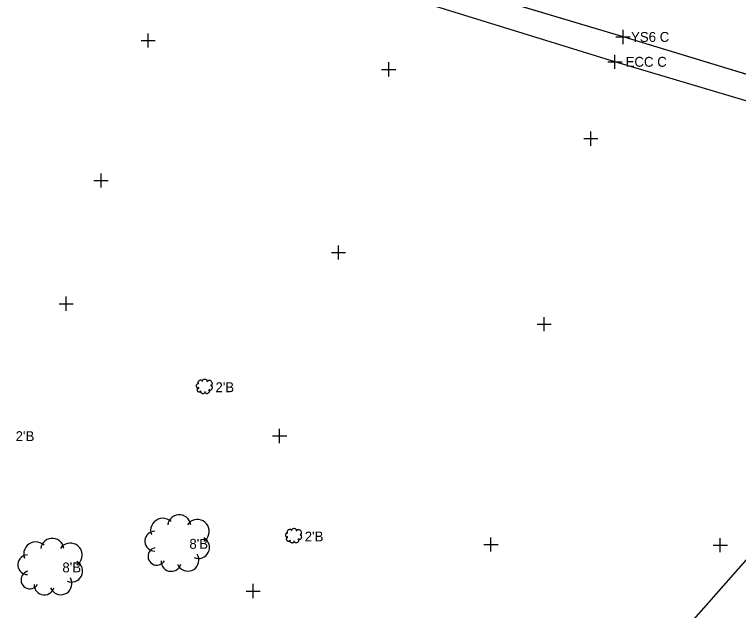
# Model space of a CAD drawing. Extents: x 1324236 to 1326110, y 459090 to 460782.
# Drawn here: x 1325080.9 to 1325183.3, y 460303.9 to 460388.2 of the extents above; entities that cross this region are included whole.
import ezdxf

# ---------------------------------------------------------------- set-up
doc = ezdxf.new("R2010")
doc.units = 0
for name, color, linetype in [('DR_X_Ditch', 7, 'Continuous'), ('DV_X_Property_Line', 7, 'Continuous'), ('E-RW-ODOT', 7, 'Continuous'), ('PM_X_Edge_Line', 7, 'Continuous'), ('PV_X_Shoulder', 7, 'Continuous'), ('RW_X_CL', 7, 'Continuous'), ('VG_X_Cells', 7, 'Continuous')]:
    doc.layers.add(name, color=color, linetype=linetype)

msp = doc.modelspace()

# ---------------------------------------------------------------- linework, layer by layer
at = {"layer": 'DR_X_Ditch'}
msp.add_lwpolyline([(1325197.01, 460375.9), (1325166.97, 460385.03), (1325137.44, 460393.89), (1325105.63, 460403.27), (1325074.39, 460412.77), (1325043.11, 460422.51), (1325010.96, 460432.4), (1324979.11, 460442.15), (1324948.44, 460451.51), (1324916.91, 460461.07), (1324885.73, 460470.56), (1324853.81, 460480.32)], dxfattribs=at)
at = {"layer": 'DV_X_Property_Line'}
for p, q in [((1325165.83, 460380.51), (1325165.83, 460382.51)), ((1325164.83, 460381.51), (1325166.83, 460381.51))]:
    msp.add_line(p, q, dxfattribs=at)
at = {"layer": 'E-RW-ODOT'}
msp.add_line((1325084.27, 460197.5), (1325254.99, 460391.14), dxfattribs=at)
at = {"layer": 'PM_X_Edge_Line'}
for p, q in [((1325166.97, 460385.03), (1325137.44, 460393.89)), ((1325197.01, 460375.9), (1325166.97, 460385.03))]:
    msp.add_line(p, q, dxfattribs=at)
at = {"layer": 'PV_X_Shoulder'}
msp.add_lwpolyline([(1325195.95, 460372.56), (1325165.83, 460381.51), (1325136.68, 460390.56), (1325104.65, 460400.42), (1325073.36, 460409.98), (1325042.02, 460419.51), (1325009.78, 460429.29), (1324978.1, 460438.94), (1324947.36, 460448.3), (1324915.86, 460458.05), (1324884.93, 460467.36), (1324852.76, 460477.1)], dxfattribs=at)
at = {"layer": 'RW_X_CL'}
for p, q in [((1325166.97, 460384.03), (1325166.97, 460386.03)), ((1325099.77, 460383.53), (1325099.77, 460385.53)), ((1325165.97, 460385.03), (1325167.97, 460385.03)), ((1325098.77, 460384.53), (1325100.77, 460384.53)), ((1325133.81, 460379.44), (1325133.81, 460381.44)), ((1325132.81, 460380.44), (1325134.81, 460380.44)), ((1325162.4, 460369.64), (1325162.4, 460371.64)), ((1325161.4, 460370.64), (1325163.4, 460370.64)), ((1325093.11, 460363.72), (1325093.11, 460365.72)), ((1325092.11, 460364.72), (1325094.11, 460364.72)), ((1325126.72, 460353.53), (1325126.72, 460355.53)), ((1325125.72, 460354.53), (1325127.72, 460354.53)), ((1325088.17, 460346.29), (1325088.17, 460348.29)), ((1325087.17, 460347.29), (1325089.17, 460347.29)), ((1325155.81, 460343.4), (1325155.81, 460345.4)), ((1325154.81, 460344.4), (1325156.81, 460344.4)), ((1325118.38, 460327.58), (1325118.38, 460329.58)), ((1325117.38, 460328.58), (1325119.38, 460328.58)), ((1325148.28, 460312.23), (1325148.28, 460314.23)), ((1325180.73, 460312.13), (1325180.73, 460314.13)), ((1325147.28, 460313.23), (1325149.28, 460313.23)), ((1325179.73, 460313.13), (1325181.73, 460313.13)), ((1325114.64, 460305.64), (1325114.64, 460307.64)), ((1325113.64, 460306.64), (1325115.64, 460306.64))]:
    msp.add_line(p, q, dxfattribs=at)
at = {"layer": 'VG_X_Cells'}
for points in [[(1325108.21, 460336.24), (1325108.19, 460336.32), (1325108.15, 460336.39), (1325108.11, 460336.45), (1325108.05, 460336.51), (1325107.99, 460336.55), (1325107.91, 460336.58), (1325107.84, 460336.59), (1325107.76, 460336.59), (1325107.68, 460336.58), (1325107.61, 460336.55), (1325107.54, 460336.51), (1325107.49, 460336.45), (1325107.44, 460336.39), (1325107.41, 460336.32), (1325107.39, 460336.24)], [(1325106.93, 460336.01), (1325106.86, 460336), (1325106.8, 460335.99), (1325106.74, 460335.96), (1325106.69, 460335.92), (1325106.65, 460335.87), (1325106.62, 460335.82), (1325106.59, 460335.76), (1325106.58, 460335.69), (1325106.58, 460335.63), (1325106.59, 460335.57), (1325106.62, 460335.51), (1325106.65, 460335.45), (1325106.69, 460335.4), (1325106.74, 460335.37), (1325106.8, 460335.34), (1325106.86, 460335.32), (1325106.93, 460335.31)], [(1325107.51, 460336.36), (1325107.44, 460336.41), (1325107.37, 460336.44), (1325107.29, 460336.47), (1325107.21, 460336.47), (1325107.13, 460336.46), (1325107.05, 460336.44), (1325106.98, 460336.4), (1325106.92, 460336.35), (1325106.86, 460336.28), (1325106.82, 460336.21), (1325106.8, 460336.14), (1325106.79, 460336.06), (1325106.79, 460335.97), (1325106.81, 460335.89)], [(1325108.67, 460335.66), (1325108.73, 460335.71), (1325108.78, 460335.77), (1325108.82, 460335.84), (1325108.84, 460335.91), (1325108.86, 460335.99), (1325108.85, 460336.07), (1325108.83, 460336.14), (1325108.8, 460336.21), (1325108.76, 460336.28), (1325108.7, 460336.33), (1325108.64, 460336.38), (1325108.57, 460336.41), (1325108.49, 460336.43), (1325108.42, 460336.43), (1325108.34, 460336.42), (1325108.26, 460336.39), (1325108.2, 460336.35), (1325108.14, 460336.3), (1325108.09, 460336.24)], [(1325108.32, 460335.08), (1325108.39, 460335.06), (1325108.47, 460335.05), (1325108.54, 460335.05), (1325108.61, 460335.07), (1325108.68, 460335.1), (1325108.74, 460335.15), (1325108.79, 460335.2), (1325108.83, 460335.26), (1325108.85, 460335.33), (1325108.87, 460335.41), (1325108.87, 460335.48), (1325108.85, 460335.55), (1325108.82, 460335.62), (1325108.78, 460335.68), (1325108.73, 460335.74), (1325108.67, 460335.78)], [(1325106.93, 460335.43), (1325106.87, 460335.41), (1325106.82, 460335.38), (1325106.77, 460335.34), (1325106.74, 460335.29), (1325106.71, 460335.23), (1325106.7, 460335.17), (1325106.69, 460335.11), (1325106.7, 460335.05), (1325106.72, 460334.99), (1325106.76, 460334.94), (1325106.8, 460334.89), (1325106.85, 460334.86), (1325106.9, 460334.83), (1325106.96, 460334.82), (1325107.02, 460334.81), (1325107.08, 460334.82), (1325107.14, 460334.84), (1325107.19, 460334.87), (1325107.24, 460334.92), (1325107.28, 460334.97)], [(1325107.16, 460334.97), (1325107.16, 460334.9), (1325107.18, 460334.83), (1325107.21, 460334.77), (1325107.25, 460334.71), (1325107.3, 460334.67), (1325107.36, 460334.63), (1325107.42, 460334.61), (1325107.49, 460334.6), (1325107.56, 460334.6), (1325107.63, 460334.61), (1325107.69, 460334.64), (1325107.75, 460334.68), (1325107.79, 460334.73), (1325107.83, 460334.79), (1325107.86, 460334.85)], [(1325107.74, 460334.85), (1325107.78, 460334.78), (1325107.82, 460334.72), (1325107.88, 460334.67), (1325107.95, 460334.64), (1325108.02, 460334.61), (1325108.09, 460334.6), (1325108.17, 460334.61), (1325108.24, 460334.63), (1325108.31, 460334.66), (1325108.37, 460334.71), (1325108.42, 460334.77), (1325108.46, 460334.83), (1325108.48, 460334.91), (1325108.49, 460334.98), (1325108.49, 460335.06), (1325108.47, 460335.13), (1325108.44, 460335.2)], [(1325105.8, 460316.02), (1325105.73, 460316.32), (1325105.6, 460316.6), (1325105.42, 460316.86), (1325105.19, 460317.07), (1325104.93, 460317.24), (1325104.64, 460317.36), (1325104.34, 460317.42), (1325104.02, 460317.42), (1325103.72, 460317.36), (1325103.43, 460317.24), (1325103.16, 460317.07), (1325102.94, 460316.86), (1325102.76, 460316.6), (1325102.63, 460316.32), (1325102.55, 460316.02)], [(1325103.02, 460316.48), (1325102.76, 460316.68), (1325102.46, 460316.82), (1325102.15, 460316.9), (1325101.82, 460316.93), (1325101.5, 460316.89), (1325101.19, 460316.79), (1325100.9, 460316.64), (1325100.65, 460316.43), (1325100.44, 460316.18), (1325100.28, 460315.9), (1325100.17, 460315.59), (1325100.13, 460315.26), (1325100.15, 460314.94), (1325100.23, 460314.62)], [(1325107.66, 460313.69), (1325107.9, 460313.89), (1325108.11, 460314.13), (1325108.26, 460314.4), (1325108.36, 460314.69), (1325108.41, 460315), (1325108.39, 460315.31), (1325108.32, 460315.61), (1325108.2, 460315.9), (1325108.02, 460316.16), (1325107.8, 460316.38), (1325107.55, 460316.55), (1325107.26, 460316.68), (1325106.96, 460316.75), (1325106.65, 460316.76), (1325106.34, 460316.71), (1325106.04, 460316.61), (1325105.77, 460316.46), (1325105.54, 460316.26), (1325105.34, 460316.02)], [(1325100.7, 460315.09), (1325100.44, 460315.06), (1325100.19, 460314.99), (1325099.96, 460314.88), (1325099.76, 460314.72), (1325099.58, 460314.53), (1325099.45, 460314.31), (1325099.36, 460314.08), (1325099.31, 460313.82), (1325099.31, 460313.57), (1325099.36, 460313.31), (1325099.45, 460313.07), (1325099.58, 460312.85), (1325099.76, 460312.66), (1325099.96, 460312.51), (1325100.19, 460312.39), (1325100.44, 460312.32), (1325100.7, 460312.3)], [(1325120.14, 460315.24), (1325120.07, 460315.29), (1325120, 460315.33), (1325119.92, 460315.35), (1325119.84, 460315.35), (1325119.76, 460315.35), (1325119.68, 460315.32), (1325119.61, 460315.28), (1325119.54, 460315.23), (1325119.49, 460315.17), (1325119.45, 460315.1), (1325119.43, 460315.02), (1325119.41, 460314.94), (1325119.42, 460314.86), (1325119.44, 460314.78)], [(1325120.83, 460315.13), (1325120.81, 460315.2), (1325120.78, 460315.27), (1325120.74, 460315.34), (1325120.68, 460315.39), (1325120.61, 460315.43), (1325120.54, 460315.46), (1325120.47, 460315.48), (1325120.39, 460315.48), (1325120.31, 460315.46), (1325120.24, 460315.43), (1325120.17, 460315.39), (1325120.12, 460315.34), (1325120.07, 460315.27), (1325120.04, 460315.2), (1325120.02, 460315.13)], [(1325121.3, 460314.55), (1325121.36, 460314.6), (1325121.41, 460314.65), (1325121.45, 460314.72), (1325121.47, 460314.8), (1325121.48, 460314.87), (1325121.48, 460314.95), (1325121.46, 460315.03), (1325121.43, 460315.1), (1325121.39, 460315.16), (1325121.33, 460315.22), (1325121.27, 460315.26), (1325121.2, 460315.29), (1325121.12, 460315.31), (1325121.04, 460315.31), (1325120.97, 460315.3), (1325120.89, 460315.28), (1325120.83, 460315.24), (1325120.77, 460315.19), (1325120.72, 460315.13)], [(1325087.84, 460312.68), (1325087.77, 460312.98), (1325087.64, 460313.27), (1325087.46, 460313.52), (1325087.23, 460313.74), (1325086.97, 460313.91), (1325086.68, 460314.02), (1325086.37, 460314.08), (1325086.06, 460314.08), (1325085.75, 460314.02), (1325085.46, 460313.91), (1325085.2, 460313.74), (1325084.97, 460313.52), (1325084.79, 460313.27), (1325084.66, 460312.98), (1325084.59, 460312.68)], [(1325106.27, 460311.37), (1325106.55, 460311.28), (1325106.84, 460311.24), (1325107.14, 460311.26), (1325107.43, 460311.33), (1325107.7, 460311.46), (1325107.94, 460311.63), (1325108.14, 460311.85), (1325108.29, 460312.1), (1325108.4, 460312.38), (1325108.45, 460312.67), (1325108.45, 460312.97), (1325108.39, 460313.26), (1325108.28, 460313.53), (1325108.11, 460313.78), (1325107.91, 460313.99), (1325107.66, 460314.16)], [(1325119.56, 460314.89), (1325119.49, 460314.89), (1325119.43, 460314.87), (1325119.37, 460314.84), (1325119.32, 460314.8), (1325119.28, 460314.76), (1325119.24, 460314.7), (1325119.22, 460314.64), (1325119.21, 460314.58), (1325119.21, 460314.51), (1325119.22, 460314.45), (1325119.24, 460314.39), (1325119.28, 460314.34), (1325119.32, 460314.29), (1325119.37, 460314.25), (1325119.43, 460314.22), (1325119.49, 460314.2), (1325119.56, 460314.2)], [(1325119.56, 460314.31), (1325119.5, 460314.29), (1325119.45, 460314.26), (1325119.4, 460314.22), (1325119.36, 460314.17), (1325119.34, 460314.11), (1325119.32, 460314.05), (1325119.32, 460313.99), (1325119.33, 460313.93), (1325119.35, 460313.87), (1325119.38, 460313.82), (1325119.42, 460313.78), (1325119.47, 460313.74), (1325119.53, 460313.71), (1325119.59, 460313.7), (1325119.65, 460313.7), (1325119.71, 460313.71), (1325119.77, 460313.73), (1325119.82, 460313.76), (1325119.87, 460313.8), (1325119.9, 460313.85)], [(1325120.37, 460313.73), (1325120.4, 460313.67), (1325120.45, 460313.61), (1325120.51, 460313.56), (1325120.57, 460313.52), (1325120.65, 460313.5), (1325120.72, 460313.49), (1325120.8, 460313.49), (1325120.87, 460313.51), (1325120.94, 460313.55), (1325121, 460313.59), (1325121.05, 460313.65), (1325121.09, 460313.72), (1325121.11, 460313.79), (1325121.12, 460313.86), (1325121.12, 460313.94), (1325121.1, 460314.01), (1325121.07, 460314.08)], [(1325120.95, 460313.97), (1325121.02, 460313.94), (1325121.09, 460313.93), (1325121.17, 460313.94), (1325121.24, 460313.96), (1325121.31, 460313.99), (1325121.37, 460314.03), (1325121.42, 460314.09), (1325121.46, 460314.15), (1325121.48, 460314.22), (1325121.5, 460314.29), (1325121.49, 460314.36), (1325121.48, 460314.44), (1325121.45, 460314.51), (1325121.41, 460314.57), (1325121.36, 460314.62), (1325121.3, 460314.66)], [(1325085.05, 460313.14), (1325084.79, 460313.34), (1325084.5, 460313.48), (1325084.18, 460313.57), (1325083.86, 460313.59), (1325083.53, 460313.55), (1325083.22, 460313.46), (1325082.93, 460313.3), (1325082.68, 460313.1), (1325082.47, 460312.85), (1325082.31, 460312.56), (1325082.21, 460312.25), (1325082.17, 460311.93), (1325082.19, 460311.6), (1325082.27, 460311.29)], [(1325089.7, 460310.36), (1325089.94, 460310.55), (1325090.14, 460310.79), (1325090.29, 460311.06), (1325090.4, 460311.35), (1325090.44, 460311.66), (1325090.43, 460311.97), (1325090.36, 460312.28), (1325090.23, 460312.56), (1325090.06, 460312.82), (1325089.84, 460313.04), (1325089.58, 460313.21), (1325089.29, 460313.34), (1325088.99, 460313.41), (1325088.68, 460313.42), (1325088.37, 460313.38), (1325088.08, 460313.28), (1325087.81, 460313.12), (1325087.57, 460312.92), (1325087.37, 460312.68)], [(1325119.79, 460313.85), (1325119.79, 460313.78), (1325119.81, 460313.71), (1325119.84, 460313.65), (1325119.88, 460313.6), (1325119.93, 460313.55), (1325119.99, 460313.52), (1325120.05, 460313.49), (1325120.12, 460313.48), (1325120.19, 460313.48), (1325120.25, 460313.5), (1325120.32, 460313.52), (1325120.37, 460313.56), (1325120.42, 460313.61), (1325120.46, 460313.67), (1325120.48, 460313.73)], [(1325100.7, 460312.76), (1325100.47, 460312.68), (1325100.26, 460312.55), (1325100.07, 460312.39), (1325099.93, 460312.19), (1325099.83, 460311.96), (1325099.77, 460311.73), (1325099.76, 460311.48), (1325099.79, 460311.24), (1325099.88, 460311.01), (1325100.01, 460310.8), (1325100.17, 460310.61), (1325100.37, 460310.47), (1325100.59, 460310.37), (1325100.83, 460310.31), (1325101.08, 460310.3), (1325101.32, 460310.33), (1325101.55, 460310.42), (1325101.76, 460310.54), (1325101.94, 460310.71), (1325102.09, 460310.91)], [(1325082.73, 460311.75), (1325082.47, 460311.73), (1325082.23, 460311.66), (1325082, 460311.54), (1325081.79, 460311.39), (1325081.62, 460311.2), (1325081.48, 460310.98), (1325081.39, 460310.74), (1325081.34, 460310.48), (1325081.34, 460310.23), (1325081.39, 460309.97), (1325081.48, 460309.74), (1325081.62, 460309.52), (1325081.79, 460309.33), (1325082, 460309.17), (1325082.23, 460309.06), (1325082.47, 460308.99), (1325082.73, 460308.96)], [(1325103.95, 460310.44), (1325104.09, 460310.17), (1325104.28, 460309.94), (1325104.51, 460309.74), (1325104.77, 460309.59), (1325105.06, 460309.5), (1325105.36, 460309.46), (1325105.67, 460309.48), (1325105.96, 460309.56), (1325106.23, 460309.7), (1325106.47, 460309.89), (1325106.67, 460310.11), (1325106.82, 460310.38), (1325106.92, 460310.66), (1325106.96, 460310.97), (1325106.94, 460311.27), (1325106.87, 460311.56), (1325106.73, 460311.84)], [(1325088.3, 460308.03), (1325088.58, 460307.94), (1325088.88, 460307.9), (1325089.17, 460307.92), (1325089.46, 460307.99), (1325089.73, 460308.12), (1325089.97, 460308.29), (1325090.17, 460308.51), (1325090.33, 460308.76), (1325090.44, 460309.04), (1325090.49, 460309.33), (1325090.48, 460309.63), (1325090.42, 460309.92), (1325090.31, 460310.19), (1325090.15, 460310.44), (1325089.94, 460310.65), (1325089.7, 460310.82)], [(1325101.62, 460310.91), (1325101.64, 460310.63), (1325101.71, 460310.37), (1325101.82, 460310.12), (1325101.99, 460309.9), (1325102.19, 460309.71), (1325102.42, 460309.57), (1325102.68, 460309.47), (1325102.95, 460309.43), (1325103.22, 460309.44), (1325103.49, 460309.5), (1325103.74, 460309.61), (1325103.97, 460309.76), (1325104.16, 460309.96), (1325104.31, 460310.19), (1325104.41, 460310.44)], [(1325082.73, 460309.43), (1325082.5, 460309.34), (1325082.29, 460309.21), (1325082.11, 460309.05), (1325081.96, 460308.85), (1325081.86, 460308.63), (1325081.8, 460308.39), (1325081.79, 460308.14), (1325081.83, 460307.9), (1325081.91, 460307.67), (1325082.04, 460307.46), (1325082.21, 460307.28), (1325082.4, 460307.13), (1325082.63, 460307.03), (1325082.87, 460306.97), (1325083.11, 460306.96), (1325083.35, 460306.99), (1325083.59, 460307.08), (1325083.8, 460307.21), (1325083.98, 460307.37), (1325084.12, 460307.57)], [(1325085.98, 460307.11), (1325086.12, 460306.84), (1325086.31, 460306.6), (1325086.54, 460306.4), (1325086.81, 460306.25), (1325087.1, 460306.16), (1325087.4, 460306.12), (1325087.7, 460306.15), (1325087.99, 460306.23), (1325088.26, 460306.36), (1325088.5, 460306.55), (1325088.7, 460306.78), (1325088.86, 460307.04), (1325088.95, 460307.33), (1325088.99, 460307.63), (1325088.98, 460307.93), (1325088.9, 460308.23), (1325088.77, 460308.5)], [(1325083.66, 460307.57), (1325083.67, 460307.3), (1325083.74, 460307.03), (1325083.86, 460306.78), (1325084.02, 460306.56), (1325084.22, 460306.38), (1325084.46, 460306.23), (1325084.71, 460306.14), (1325084.98, 460306.09), (1325085.26, 460306.1), (1325085.53, 460306.16), (1325085.78, 460306.27), (1325086, 460306.43), (1325086.19, 460306.62), (1325086.34, 460306.85), (1325086.45, 460307.11)]]:
    msp.add_lwpolyline(points, dxfattribs=at)

# ---------------------------------------------------------------- texts
at = {"layer": 'DV_X_Property_Line'}
msp.add_text('ECC C', height=1.4, dxfattribs=at).set_placement((1325167.33, 460380.81))
at = {"layer": 'RW_X_CL'}
msp.add_text('YS6 C', height=1.4, dxfattribs=at).set_placement((1325168.1, 460384.33))
at = {"layer": 'VG_X_Cells'}
for s, p in [("2'B", (1325109.3, 460334.77)), ("2'B", (1325081.03, 460327.85)), ("2'B", (1325121.93, 460313.65)), ("8'B", (1325105.61, 460312.62)), ("8'B", (1325087.64, 460309.28))]:
    msp.add_text(s, height=1.4, dxfattribs=at).set_placement(p)

doc.saveas('drawing.dxf')
